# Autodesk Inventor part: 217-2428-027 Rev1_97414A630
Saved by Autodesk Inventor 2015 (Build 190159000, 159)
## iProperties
Created: 2014-11
Part Number: 217-2428-027 Rev1_97414A630
Material: Generic
Document SubType Name: Modeling
Designer: User
Density: 1 g/cm^3
Appearance: Default
Author: User
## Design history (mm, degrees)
node "217-2428-027 Rev1_97414A630.ipt1"
node "Extrude1"
node "Base1"
